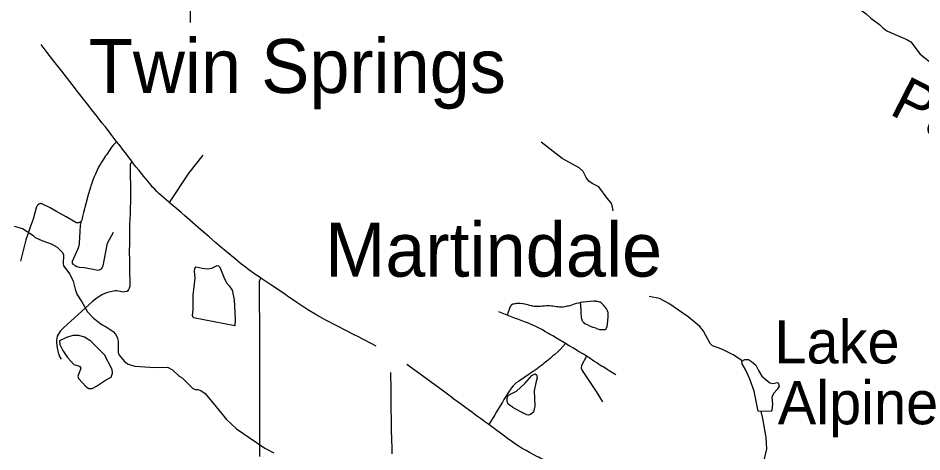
# Model space of a CAD drawing. Extents: x -19 to 366, y -4 to 359.
# Drawn here: x 143.105 to 144.78, y 189.689 to 190.492 of the extents above; entities that cross this region are included whole.
import ezdxf

# ---------------------------------------------------------------- set-up
doc = ezdxf.new("R2010")
doc.units = 0
for name, color, linetype in [('R_Horz Alg Annot', 7, 'Continuous'), ('R_ROW', 7, 'Continuous'), ('R_ROW Annot', 7, 'Continuous'), ('R_Temp Easement', 7, 'Continuous'), ('Sheet Fence', 7, 'Continuous')]:
    doc.layers.add(name, color=color, linetype=linetype)

msp = doc.modelspace()

# ---------------------------------------------------------------- linework, layer by layer
at = {"layer": 'R_ROW'}
for points in [[(143.2873, 190.2627), (143.2846, 190.2662), (143.2831, 190.2687), (143.2756, 190.2784), (143.2666, 190.2901), (143.2603, 190.2981), (143.2517, 190.3091), (143.241, 190.3227), (143.2358, 190.3293), (143.231, 190.3354), (143.217, 190.3536), (143.2053, 190.3686), (143.1859, 190.3935), (143.1713, 190.412), (143.1588, 190.4279), (143.151, 190.4379), (143.1473, 190.4426)], [(143.2873, 190.2627), (143.2815, 190.2572), (143.2786, 190.2533), (143.2768, 190.2507), (143.275, 190.248), (143.2691, 190.2394), (143.267, 190.2364), (143.2652, 190.2338), (143.263, 190.2305), (143.2594, 190.2248), (143.2569, 190.2207), (143.2557, 190.2185), (143.254, 190.2155), (143.2513, 190.2102), (143.2492, 190.2056), (143.248, 190.2028), (143.247, 190.2005), (143.2459, 190.1976), (143.2442, 190.1934), (143.2408, 190.1842), (143.2397, 190.181), (143.2388, 190.1784), (143.2358, 190.1685), (143.2347, 190.1651), (143.234, 190.1623), (143.2301, 190.1478), (143.2262, 190.1321), (143.2238, 190.1218), (143.2233, 190.1198), (143.2227, 190.1179), (143.2221, 190.1164), (143.2216, 190.1155)], [(143.2873, 190.2627), (143.2899, 190.2593), (143.2916, 190.2575), (143.2998, 190.2468), (143.3033, 190.2423), (143.3121, 190.2308), (143.3156, 190.2263)], [(143.3848, 190.1504), (143.383, 190.1519), (143.3743, 190.1595), (143.3696, 190.1636), (143.3656, 190.1672), (143.3622, 190.1705), (143.3574, 190.1754), (143.3541, 190.179), (143.3512, 190.1824), (143.3419, 190.1934), (143.3376, 190.1986), (143.3289, 190.2095), (143.3233, 190.2165), (143.3156, 190.2263)], [(143.2216, 190.1155), (143.221, 190.1149), (143.2201, 190.1142), (143.2186, 190.1133), (143.2179, 190.113), (143.2174, 190.1129), (143.2155, 190.1126), (143.2143, 190.1126), (143.2134, 190.1127), (143.2127, 190.1129), (143.212, 190.1132), (143.1937, 190.1239), (143.1817, 190.1307), (143.176, 190.1339), (143.1641, 190.1403), (143.1615, 190.1417), (143.1502, 190.1474), (143.1492, 190.1478), (143.1481, 190.1482), (143.1468, 190.1482), (143.1456, 190.1481), (143.145, 190.148), (143.1444, 190.1478), (143.1434, 190.1474), (143.1425, 190.1469), (143.142, 190.1465), (143.1414, 190.146), (143.1408, 190.1454), (143.14, 190.1443), (143.1394, 190.1431), (143.1391, 190.142), (143.1348, 190.1268), (143.1339, 190.1238), (143.1325, 190.1195), (143.1291, 190.1093), (143.1281, 190.1062), (143.1231, 190.0918), (143.1225, 190.0899), (143.1199, 190.0831), (143.1191, 190.081), (143.109, 190.0419)], [(143.5549, 190.0101), (143.5515, 190.0124), (143.5452, 190.0167), (143.5413, 190.0195), (143.5323, 190.0259), (143.5259, 190.0305), (143.5211, 190.0342), (143.5172, 190.0373), (143.5118, 190.0417), (143.5068, 190.0458), (143.4903, 190.0597), (143.4801, 190.0682), (143.4713, 190.0757), (143.4586, 190.0865), (143.4471, 190.0964), (143.4433, 190.0998), (143.4132, 190.126), (143.4076, 190.1309), (143.4024, 190.1354), (143.3848, 190.1504)], [(143.2216, 190.1155), (143.2197, 190.1086), (143.2182, 190.0744), (143.2174, 190.0702), (143.2158, 190.0645), (143.2051, 190.0411), (143.2048, 190.0383), (143.2065, 190.0361), (143.2103, 190.0336), (143.2139, 190.0319), (143.2162, 190.031), (143.2189, 190.0304), (143.2277, 190.0297), (143.2499, 190.0254), (143.2529, 190.0251), (143.2558, 190.0258), (143.2592, 190.0278), (143.2609, 190.0296), (143.2625, 190.0331), (143.2705, 190.075), (143.2817, 190.0953)], [(143.553, 189.6799), (143.5529, 189.7075), (143.5529, 189.7196), (143.5529, 189.7286), (143.5528, 189.7397), (143.5528, 189.7433), (143.5527, 189.7504), (143.5527, 189.7584), (143.5526, 189.767), (143.5526, 189.7726), (143.5527, 189.784), (143.5526, 189.7967), (143.5526, 189.8101), (143.5526, 189.8196), (143.5526, 189.8231), (143.5527, 189.837), (143.5528, 189.8474), (143.5526, 189.8633), (143.5526, 189.8735), (143.5526, 189.8818), (143.5526, 189.8893), (143.5527, 189.8961), (143.5527, 189.9008), (143.5527, 189.9055), (143.5526, 189.9148), (143.5526, 189.922), (143.5525, 189.9389), (143.5524, 189.9548), (143.5524, 189.969), (143.5524, 189.9796), (143.5524, 189.9856), (143.5523, 189.9964), (143.5522, 190.0006), (143.5523, 190.0027), (143.5524, 190.0044), (143.5525, 190.0056), (143.5527, 190.0064), (143.553, 190.0073), (143.5533, 190.008), (143.5549, 190.0101)], [(143.7684, 189.8846), (143.759, 189.8894), (143.7334, 189.9026), (143.73, 189.9044), (143.6953, 189.9219), (143.6737, 189.9332), (143.6696, 189.9353), (143.6581, 189.9417), (143.6419, 189.9514), (143.6215, 189.9653), (143.6042, 189.9772), (143.601, 189.9794), (143.5964, 189.9824), (143.5734, 189.9977), (143.5549, 190.0101)], [(144.0108, 189.9418), (143.9955, 189.9477)], [(144.1194, 189.8891), (144.1023, 189.8992), (144.0954, 189.9033), (144.0898, 189.9065), (144.0864, 189.9085), (144.082, 189.9111), (144.0752, 189.9151), (144.0719, 189.917), (144.0682, 189.9189), (144.0631, 189.9214), (144.0599, 189.9229), (144.053, 189.9259), (144.0488, 189.9274), (144.0429, 189.9296), (144.037, 189.9318), (144.0339, 189.9329), (144.0311, 189.9341), (144.0288, 189.935), (144.0268, 189.9357), (144.0108, 189.9418)], [(144.1194, 189.8891), (144.1096, 189.8787), (144.1063, 189.8754), (144.0992, 189.8692), (144.096, 189.8665), (144.0912, 189.8622), (144.087, 189.8586), (144.0847, 189.8567), (144.0821, 189.8545), (144.0789, 189.852), (144.0766, 189.85), (144.0727, 189.8471), (144.0709, 189.8458), (144.068, 189.8437), (144.0665, 189.8426), (144.0611, 189.8386), (144.0595, 189.8374), (144.0563, 189.8353), (144.054, 189.8338), (144.0498, 189.8312), (144.0473, 189.8294), (144.0446, 189.8277), (144.0419, 189.8259), (144.0318, 189.8191), (144.0277, 189.8162), (144.0267, 189.8155), (144.0251, 189.8142), (144.0238, 189.813), (144.0219, 189.811), (144.0185, 189.8069), (144.0177, 189.8056), (144.0134, 189.7991), (144.0097, 189.7929), (144.0052, 189.7858), (144.0022, 189.7807), (143.9982, 189.774), (143.9916, 189.7626), (143.9884, 189.7573), (143.9768, 189.7391)], [(144.158, 189.8659), (144.1573, 189.8663), (144.1523, 189.8695), (144.1446, 189.8739), (144.1427, 189.875), (144.1379, 189.8781), (144.1358, 189.8794), (144.1327, 189.8814), (144.1286, 189.8839), (144.126, 189.8852), (144.1194, 189.8891)], [(144.158, 189.8659), (144.1491, 189.8484), (144.1482, 189.8436), (144.1499, 189.8394), (144.1761, 189.8004), (144.1879, 189.7811)], [(144.2127, 189.8315), (144.2, 189.8387), (144.1963, 189.8411), (144.1919, 189.844), (144.189, 189.8458), (144.1873, 189.8467), (144.1839, 189.8488), (144.1806, 189.8511), (144.1771, 189.8533), (144.1729, 189.8558), (144.1714, 189.8568), (144.1689, 189.8585), (144.1672, 189.8598), (144.1643, 189.862), (144.1613, 189.8638), (144.158, 189.8659)], [(143.9768, 189.7391), (143.9695, 189.7444), (143.9658, 189.7471), (143.9615, 189.7503), (143.9581, 189.7528), (143.9534, 189.7562), (143.9487, 189.7597), (143.9473, 189.7607), (143.9345, 189.7701), (143.9295, 189.7737), (143.9243, 189.7778), (143.9125, 189.7864), (143.9055, 189.7916), (143.8958, 189.7989), (143.8771, 189.8126), (143.8711, 189.817), (143.8633, 189.8226), (143.8565, 189.8275), (143.8252, 189.8505)], [(143.7949, 189.8358), (143.795, 189.8304), (143.795, 189.8272), (143.7955, 189.8119), (143.7955, 189.8084), (143.7954, 189.7925), (143.7953, 189.7861), (143.7953, 189.783), (143.7954, 189.772), (143.7955, 189.7671), (143.7959, 189.749), (143.7963, 189.7343), (143.7964, 189.7301), (143.7964, 189.7228), (143.7965, 189.7182), (143.7966, 189.7133), (143.7972, 189.6943), (143.7973, 189.6851)], [(144.0894, 189.669), (144.0789, 189.674), (144.0724, 189.6772), (144.0695, 189.6786), (144.0673, 189.6797), (144.0616, 189.6827), (144.0524, 189.6876), (144.0463, 189.6909), (144.0424, 189.6932), (144.0391, 189.6952), (144.0312, 189.7001), (144.0265, 189.7032), (144.0193, 189.7083), (144.0142, 189.7118), (144.0095, 189.7152), (144.0064, 189.7175), (144.0011, 189.7214), (143.9869, 189.7317), (143.9768, 189.7391)]]:
    msp.add_lwpolyline(points, dxfattribs=at)
at = {"layer": 'R_ROW Annot'}
for points in [[(143.426, 190.7147), (143.4234, 190.4833)], [(143.4469, 190.2377), (143.4214, 190.2053), (143.3848, 190.1504)], [(143.3156, 190.2263), (143.3142, 190.2245), (143.3136, 190.2234), (143.3127, 190.2201), (143.3124, 190.2184), (143.3124, 190.2167), (143.3127, 190.2073), (143.3128, 190.2055), (143.313, 190.1775), (143.313, 190.1561), (143.3128, 190.1359), (143.3126, 190.1327), (143.3117, 190.1166), (143.3115, 190.1125), (143.3114, 190.1094), (143.3114, 190.1073), (143.3114, 190.1019), (143.3114, 190.0996), (143.3115, 190.0938), (143.3115, 190.0901), (143.3114, 190.0871), (143.3114, 190.0827), (143.3115, 190.0788), (143.3114, 190.0752), (143.3113, 190.0731), (143.3112, 190.0693), (143.3109, 190.0637), (143.3107, 190.0568), (143.3107, 190.0552), (143.3108, 190.0536), (143.311, 190.0494), (143.3112, 190.0455), (143.3113, 190.0428), (143.3113, 190.0363), (143.3112, 190.0337), (143.3111, 190.0288), (143.311, 190.0264), (143.311, 190.0236), (143.3112, 190.0207), (143.3114, 190.0173), (143.3119, 190.0091), (143.312, 190.0067), (143.3121, 190.0037), (143.3121, 190.0019), (143.3121, 189.9988), (143.3121, 189.9972), (143.3119, 189.9956), (143.3117, 189.9942), (143.3115, 189.9935), (143.3108, 189.9917), (143.3105, 189.991), (143.31, 189.9901), (143.3095, 189.9891), (143.3084, 189.9876), (143.3068, 189.9858), (143.3028, 189.9849), (143.2999, 189.9846), (143.2969, 189.9851), (143.2875, 189.987), (143.2847, 189.9868), (143.2704, 189.9835), (143.2655, 189.9818), (143.2613, 189.9799), (143.2511, 189.9736), (143.243, 189.9673), (143.1892, 189.9182), (143.1837, 189.9126), (143.179, 189.9062), (143.1775, 189.903), (143.1765, 189.8993), (143.176, 189.8952), (143.176, 189.8905), (143.177, 189.881), (143.179, 189.8727), (143.1816, 189.8654), (143.1846, 189.8602)], [(144.1466, 189.965), (144.1456, 189.9648), (144.1432, 189.9641), (144.139, 189.9631), (144.1351, 189.9619), (144.132, 189.9608), (144.1291, 189.9599), (144.1269, 189.9592), (144.1249, 189.9587), (144.1224, 189.9581), (144.1198, 189.9576), (144.1178, 189.9571), (144.1146, 189.9566), (144.1125, 189.9565), (144.1093, 189.9566), (144.1073, 189.9567), (144.1049, 189.9569), (144.1022, 189.9572), (144.0991, 189.9577), (144.0958, 189.9581), (144.0932, 189.9584), (144.0894, 189.9588), (144.0878, 189.9589), (144.0852, 189.9589), (144.0836, 189.9589), (144.0805, 189.9586), (144.0758, 189.9582), (144.0727, 189.9578), (144.0696, 189.9576), (144.068, 189.9575), (144.066, 189.9575), (144.0634, 189.9577), (144.0614, 189.958), (144.0582, 189.9586), (144.0572, 189.9588), (144.0554, 189.9592), (144.0533, 189.9597), (144.0511, 189.9604), (144.046, 189.9617), (144.0444, 189.9621), (144.0406, 189.9629), (144.0395, 189.963), (144.035, 189.9634), (144.0328, 189.9635), (144.0308, 189.9635), (144.0286, 189.9633), (144.0265, 189.963), (144.025, 189.9628), (144.023, 189.9623), (144.0216, 189.9619), (144.0187, 189.9603), (144.0182, 189.9598), (144.0172, 189.9585), (144.0165, 189.9575), (144.0108, 189.9418)], [(144.1466, 189.965), (144.1473, 189.952), (144.1475, 189.949), (144.1476, 189.9475), (144.1478, 189.9433), (144.1479, 189.9407), (144.1479, 189.939), (144.148, 189.9376), (144.1492, 189.9336), (144.1497, 189.9323), (144.1501, 189.9314), (144.1512, 189.9299), (144.1519, 189.929), (144.1524, 189.9285), (144.1532, 189.9278), (144.1564, 189.9257), (144.1591, 189.9242), (144.1638, 189.9221), (144.1681, 189.9204), (144.1698, 189.9197), (144.1707, 189.9194), (144.1745, 189.9181), (144.1761, 189.9175), (144.1766, 189.9173), (144.1808, 189.9159), (144.1824, 189.9155), (144.1829, 189.9154), (144.1856, 189.915), (144.1872, 189.9149), (144.1886, 189.9149), (144.1905, 189.9149), (144.1927, 189.9155), (144.1943, 189.9165), (144.1953, 189.9175), (144.196, 189.9193), (144.1966, 189.9213), (144.1969, 189.9242), (144.1969, 189.9253), (144.1983, 189.9389), (144.1983, 189.9438), (144.198, 189.9465), (144.1977, 189.9479), (144.1972, 189.9497), (144.1965, 189.9511), (144.1957, 189.9525), (144.1949, 189.9537), (144.1937, 189.9552), (144.1933, 189.9558), (144.1923, 189.9569), (144.1901, 189.9594), (144.1878, 189.9621), (144.1869, 189.963), (144.1852, 189.9643), (144.1834, 189.9655), (144.183, 189.9657), (144.181, 189.9665), (144.1804, 189.9667), (144.1787, 189.967), (144.1778, 189.9672), (144.1762, 189.9673), (144.1751, 189.9674), (144.1714, 189.9674), (144.1521, 189.9656), (144.1488, 189.9652), (144.1466, 189.965)]]:
    msp.add_lwpolyline(points, dxfattribs=at)
at = {"layer": 'R_Temp Easement'}
for points in [[(144.5984, 190.55), (144.6188, 190.5349), (144.6464, 190.5209), (144.6763, 190.4994), (144.6848, 190.4913), (144.701, 190.4796), (144.7079, 190.473), (144.7147, 190.468), (144.7212, 190.465), (144.7516, 190.4519), (144.759, 190.4479), (144.7766, 190.4248), (144.7966, 190.4086)], [(144.2075, 190.1349), (144.2057, 190.1447), (144.2038, 190.1494), (144.1962, 190.1585), (144.1807, 190.1793), (144.1726, 190.1838), (144.1684, 190.1855), (144.1625, 190.19), (144.1577, 190.1963), (144.1518, 190.2077), (144.1447, 190.2146), (144.113, 190.2318), (144.0741, 190.2618)], [(143.0975, 190.1066), (143.1127, 190.1019), (143.1319, 190.0898), (143.1367, 190.0853), (143.1487, 190.0798), (143.166, 190.0736), (143.1774, 190.0676), (143.1871, 190.0578), (143.1892, 190.0536), (143.1883, 190.0365), (143.1891, 190.0329), (143.2005, 190.0178), (143.2069, 190.0047), (143.2103, 189.9897), (143.2136, 189.9804), (143.2232, 189.9662), (143.2333, 189.9478), (143.2443, 189.9359), (143.2607, 189.9238), (143.2683, 189.9201), (143.2811, 189.9112), (143.2851, 189.9065), (143.2889, 189.8995), (143.2901, 189.8926), (143.2905, 189.8729), (143.2921, 189.8676), (143.3027, 189.8551), (143.309, 189.851), (143.3214, 189.8476), (143.358, 189.8451), (143.3817, 189.8452), (143.391, 189.8407), (143.4036, 189.829), (143.4089, 189.8256), (143.4289, 189.8059), (143.4333, 189.8042), (143.4377, 189.804), (143.4436, 189.802), (143.4514, 189.7965), (143.4721, 189.7721), (143.4907, 189.7484), (143.5095, 189.7312), (143.5333, 189.7154), (143.5618, 189.6956), (143.5788, 189.6871)], [(143.4301, 189.9365), (143.4282, 189.9409), (143.4293, 189.9525), (143.4293, 189.9789), (143.4328, 190.01), (143.432, 190.0235), (143.4322, 190.0282), (143.4348, 190.0313), (143.4462, 190.0289), (143.4559, 190.0278), (143.464, 190.0287), (143.4735, 190.0337), (143.476, 190.033), (143.4788, 190.0303), (143.4859, 190.0121), (143.4913, 190.0017), (143.496, 189.9958), (143.5018, 189.9879), (143.5054, 189.9703), (143.5073, 189.9336), (143.5064, 189.9222)], [(144.4089, 189.8786), (144.3917, 189.8852), (144.3875, 189.8893), (144.3748, 189.9119), (144.368, 189.9209), (144.3465, 189.9387), (144.3105, 189.9632), (144.2936, 189.9725), (144.2742, 189.9763)], [(143.5064, 189.9222), (143.4301, 189.9365)], [(143.267, 189.8212), (143.2771, 189.8271), (143.2799, 189.8341), (143.2793, 189.8413), (143.2651, 189.8684), (143.2394, 189.8938), (143.2278, 189.9013), (143.2173, 189.9043), (143.206, 189.9044), (143.1946, 189.9006), (143.1817, 189.8943), (143.1819, 189.8874), (143.1875, 189.8766), (143.1965, 189.8634), (143.2081, 189.8507), (143.2185, 189.8475), (143.221, 189.8439), (143.2182, 189.835), (143.2158, 189.8289), (143.2166, 189.8242), (143.231, 189.8092), (143.2362, 189.806), (143.2419, 189.8061), (143.25, 189.8101)], [(144.4867, 189.6703), (144.4923, 189.6944), (144.4908, 189.7155), (144.4848, 189.7502), (144.4817, 189.7633), (144.476, 189.764), (144.4685, 189.801), (144.4606, 189.8234), (144.4535, 189.8397), (144.4464, 189.8516), (144.4457, 189.8577), (144.4299, 189.8682), (144.4089, 189.8786)], [(144.4458, 189.8565), (144.4515, 189.8594), (144.4582, 189.8594), (144.4641, 189.856), (144.4717, 189.8494), (144.4767, 189.8394), (144.4832, 189.8286), (144.498, 189.8165), (144.5031, 189.815), (144.5122, 189.8171), (144.5139, 189.8149), (144.5149, 189.8105), (144.5113, 189.804), (144.5053, 189.7974), (144.5025, 189.7928), (144.5017, 189.7896), (144.5029, 189.7778), (144.5014, 189.766), (144.5005, 189.7643), (144.4817, 189.7633)], [(144.0208, 189.7714), (144.0132, 189.777), (144.0111, 189.7822), (144.0109, 189.7888), (144.0133, 189.7936), (144.0281, 189.8012), (144.0436, 189.815), (144.0568, 189.8298), (144.0625, 189.8329), (144.0652, 189.831), (144.0667, 189.8255), (144.0641, 189.8166), (144.0613, 189.8017), (144.0622, 189.7733), (144.0596, 189.7619), (144.0545, 189.7579), (144.0507, 189.7569), (144.0475, 189.7573), (144.0399, 189.761)], [(143.25, 189.8101), (143.267, 189.8212)], [(144.0208, 189.7714), (144.0399, 189.761)]]:
    msp.add_lwpolyline(points, dxfattribs=at)
at = {"layer": 'Sheet Fence'}
for points in [[(146.7783, 1.697), (146.5788, 10.3131), (146.3785, 18.9294), (146.1776, 27.5458), (145.9759, 36.1624), (145.7736, 44.7791), (145.5705, 53.396), (145.3668, 62.013), (145.1624, 70.6301), (144.9572, 79.2474), (144.7514, 87.8648), (144.5449, 96.4823), (144.3377, 105.1), (144.1299, 113.7179), (143.9213, 122.3359), (143.712, 130.954), (143.5021, 139.5723), (143.2915, 148.1907), (143.0802, 156.8092), (142.8682, 165.4279), (142.6555, 174.0468), (142.4422, 182.6658), (142.2282, 191.2849), (142.0135, 199.9042), (141.7981, 208.5236), (141.582, 217.1432), (141.3653, 225.7629), (141.1479, 234.3828), (140.9298, 243.0028), (140.711, 251.623), (140.4916, 260.2433), (140.2715, 268.8638), (140.0508, 277.4844), (139.8293, 286.1051), (139.6072, 294.726), (139.3845, 303.3471), (139.161, 311.9683), (138.937, 320.5896), (138.7122, 329.2111), (138.4868, 337.8328), (138.2607, 346.4546)], [(0, 189.5162), (7.1121, 189.5206), (14.2243, 189.5339), (21.3364, 189.556), (28.4484, 189.5869), (35.5605, 189.6267), (42.6725, 189.6754), (49.7844, 189.7329), (56.8962, 189.7992), (64.0079, 189.8744), (71.1196, 189.9584), (78.2311, 190.0512), (85.3425, 190.1529), (92.4538, 190.2635), (99.5649, 190.3829), (106.6759, 190.5111), (113.7867, 190.6482), (120.8974, 190.7941), (128.0078, 190.9489), (135.1181, 191.1125), (142.2282, 191.2849), (149.338, 191.4662), (156.4476, 191.6563), (163.5569, 191.8553), (170.666, 192.0631), (177.7749, 192.2798), (184.8835, 192.5053), (191.9917, 192.7396), (199.0997, 192.9828), (206.2074, 193.2348), (213.3147, 193.4956), (220.4218, 193.7653), (227.5285, 194.0438), (234.6348, 194.3312), (241.7408, 194.6274), (248.8464, 194.9324), (255.9516, 195.2463), (263.0564, 195.569), (270.1608, 195.9005), (277.2648, 196.2409), (284.3683, 196.5901), (291.4715, 196.9481), (298.5741, 197.315), (305.6763, 197.6907), (312.7781, 198.0753), (319.8793, 198.4686), (326.9801, 198.8708), (334.0804, 199.2818), (341.1801, 199.7017)], [(0, 180.8999), (7.1228, 180.9044), (14.2457, 180.9176), (21.3685, 180.9397), (28.4912, 180.9706), (35.614, 181.0103), (42.7366, 181.0589), (49.8592, 181.1163), (56.9818, 181.1825), (64.1042, 181.2575), (71.2266, 181.3414), (78.3488, 181.4341), (85.4709, 181.5357), (92.5929, 181.646), (99.7147, 181.7652), (106.8364, 181.8933), (113.9579, 182.0301), (121.0793, 182.1758), (128.2005, 182.3303), (135.3214, 182.4936), (142.4422, 182.6658), (149.5627, 182.8468), (156.683, 183.0366), (163.8031, 183.2352), (170.9229, 183.4427), (178.0425, 183.659), (185.1617, 183.8841), (192.2807, 184.1181), (199.3994, 184.3608), (206.5178, 184.6124), (213.6359, 184.8728), (220.7537, 185.1421), (227.8711, 185.4201), (234.9881, 185.707), (242.1048, 186.0027), (249.2212, 186.3073), (256.3371, 186.6206), (263.4526, 186.9428), (270.5678, 187.2738), (277.6825, 187.6136), (284.7968, 187.9622), (291.9107, 188.3197), (299.0241, 188.6859), (306.1371, 189.061), (313.2495, 189.4449), (320.3615, 189.8377), (327.4731, 190.2392), (334.5841, 190.6495), (341.6946, 191.0687)]]:
    msp.add_spline(points, degree=3, dxfattribs=at)

# ---------------------------------------------------------------- texts
at = {"layer": 'R_Horz Alg Annot'}
for s, p in [('Twin Springs', (143.2358, 190.353)), ('Martindale', (143.6739, 190.0131))]:
    msp.add_text(s, height=0.1, dxfattribs=at).set_placement(p)
at = {"layer": 'R_Temp Easement'}
msp.add_text('Payne', height=0.08, rotation=332.9792, dxfattribs=at).set_placement((144.7169, 190.315))
for s, p in [('Lake', (144.5063, 189.8523)), ('Alpine', (144.5125, 189.7397))]:
    msp.add_text(s, height=0.08, dxfattribs=at).set_placement(p)

doc.saveas('drawing.dxf')
